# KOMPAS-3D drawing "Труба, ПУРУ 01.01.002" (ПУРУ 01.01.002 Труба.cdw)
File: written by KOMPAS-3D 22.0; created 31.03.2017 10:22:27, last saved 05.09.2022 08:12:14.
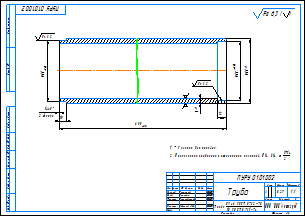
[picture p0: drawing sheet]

Sheet 1: A3, landscape

Document properties: Автор: cons; Полное имя файла: D:\Вован\Антиград\Град\ПУРУ 00.00.000 Установка пусковая ручная Элия-Р\ПУРУ 01.00.000 Стойка\ПУРУ 01.01.000 Ось\Чертежи\ПУРУ 01.01.002 Труба.cdw; Масса: 8.2938; Знак неуказанной шероховатости: 4; Параметр неуказанной шероховатости: Ra 6,3

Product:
- Body: Тело 1
    Материал: Труба$d89x6 ГОСТ 8732-78;10 ГОСТ 8731-74$ (density 7856 kg/m3)
- Part/product: Труба  | designation ПУРУ 01.01.002
    Материал: Труба$d89x6 ГОСТ 8732-78;10 ГОСТ 8731-74$ (density 7856 kg/m3)
    Масса: 8.2938
    Раздел спецификации: Детали
    Форматы листов документа: A3
    source file: ..\ПУРУ 01.01.002 Труба.m3d, ПУРУ 01.01.002 Труба.cdw
- Part/product: (unnamed)  | designation 1
- Part/product: (unnamed)  | designation 2
- Part/product: (unnamed)  | designation 3

Title block, sheet 1: Наименование: Труба; designation: ПУРУ 01.01.002; Материал: Труба 89x6 ГОСТ 8732-78 10 ГОСТ 8731-74; Масса: 8,29; Количество листов документа: 1; organisation: ООО "НПЦ"Антиград"; Форматы листов документа: A3; Литера: А; stored path: D:\РУ 00.00.000 Установка противоградовая ручная\РУ 01.00.000 Стойка\РУ 01.01.000 Ось\Чертежи\РУ 01.01.002 Труба.cdw; Разработал: Грицунов; Проверил: Налоева; Т. контр.: Семеновский; Н. контр.: Абшаев А.М.; Разработал, date: 03.04.2017; Проверил, date: 03.04.2017; Т. контр., date: 03.04.2017; Н. контр., date: 03.04.2017

Views: Вид 1, Местный разрез 1, Спереди
Referenced files in D:\Град\ПУРУ 00.00.000 Установка пусковая ручная Элия-Р\ПУРУ 01.00.000 Стойка\ПУРУ 01.01.000 Ось\: ПУРУ 01.01.002 Труба.m3d
Referenced files in D:\Вован\Антиград\Град\ПУРУ 00.00.000 Установка пусковая ручная Элия-Р\ПУРУ 01.00.000 Стойка\ПУРУ 01.01.000 Ось\: ПУРУ 01.01.002 Труба.m3d
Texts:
  Ra 3,2
  Ra 6,3
  Ra 6,3 ( )
  ПУРУ 01.01.002 Труба
Dimensions and other numbers on the sheet: 82; 89; 6; 85; 1; 2 фаски; 10; 12; 685; 1:1; 8,29; 03.04.2017

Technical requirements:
  * Размеры для справок.
  Неуказанные предельные отклонения размеров: H14, h14,    IT14 2 .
